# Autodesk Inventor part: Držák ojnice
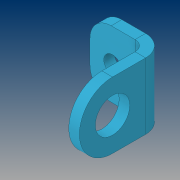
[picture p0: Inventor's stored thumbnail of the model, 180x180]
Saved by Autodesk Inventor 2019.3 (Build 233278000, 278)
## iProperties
Created: 2019-02
Part Number: Držák ojnice
Material: Ocel, legovaná
Document SubType Name: Plech
Designer: B-hon
Density: 7.73 g/cm^3
Sheet Metal Rule: Výchozí_mm
Appearance: Tyrkysová
Author: B-hon
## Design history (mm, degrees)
node "Plocha1"
  sketch "Náčrt1"
    geometry: L1 (-12.5, 12.5)-(12.5, 12.5); L2 (12.5, 12.5)-(12.5, -12.5); L3 (12.5, -12.5)-(-12.5, -12.5); L4 (-12.5, -12.5)-(-12.5, 12.5); L5 (-12.5, 12.5)-(12.5, -12.5); L6 (12.5, 12.5)-(-12.5, -12.5); 1 further point
    constraints: 12 end point, 2 midpoint, 2 parallel, 1 horizontal, 1 perpendicular
    dimensions: "d0" = 25 distance of L2.end L3.end; "d1" = 25 distance of L1.end L2.end
node "Obruba1"
fillet "Zaoblení1" dims "d13" = 12.5
sketch "Náčrt3"
  geometry: A1 r 12.5 centre (12.5, 12.5) between (12.5, 0) and (12.5, 25) reference; 2 further points
  constraints: 1 coincident
hole "Díra1" sketch "Náčrt3" at (12.5, 12.5) diameter "d14" = 13; stored, may be unused: countersink angle "d18" = 90 deg, drill point angle "d20" = 118 deg; dims "d15" = 6, "d16" = 10.5, "d17" = 2, "d19" = 4 (= Tloušťka)
fillet "Zaoblení2" dims "d21" = 8
sketch "Náčrt4"
  geometry: L1 (-12.5, -4.5)-(-12.5, 4.5) reference; L2 (-4.5, 12.5)-(4.5, 12.5) reference; 2 further points
  dimensions: "d22" = 8.5 distance from line of L1 point (-4, 0); "d23" = 12.5 distance from line of L2 point (-4, 0)
hole "Díra2" sketch "Náčrt4" at (-4, 0) diameter "d24" = 6.6; stored, may be unused: countersink angle "d28" = 90 deg, drill point angle "d30" = 118 deg; dims "d25" = 6, "d26" = 10.5, "d27" = 2, "d29" = 4 (= Tloušťka)
node "Těleso1"
feature "Deska1" dims "d2" = 4 (= Tloušťka)
sketch "Náčrt2"
  geometry: L1 through (-12.5, 0) direction (1, 0); L2 through (0, 16.5) direction (0, 1); L3 (0, 33)-(-25, 33); L4 (-25, 33)-(-25, 0)
  constraints: 6 end point, 1 horizontal, 1 perpendicular, 1 vertical
feature "Deska2" dims "d2" = 4 (= Tloušťka), "d3" = 4 (= ŠířkaVýštipu), "d4" = 2 (= HloubkaVýštipu), "d5" = 8 (= MinimálníZbytek), "d6" = 4 (= PřechodovýPoloměr), "d7" = 33, "d8" = 90 deg, "d9" = 4 (= PoloměrOhybu), "d10" = 16 (= VelikostRohovéhoVýštipu), "d11" = 4 (= VelikostMezery), "d12" = 4 (= VelikostJacobihoPoloměru), "MezeraVystřižení" = 0.01
feature "Ohyb1" dims "d2" = 4 (= Tloušťka), "d3" = 4 (= ŠířkaVýštipu), "d4" = 2 (= HloubkaVýštipu), "d5" = 8 (= MinimálníZbytek), "d6" = 4 (= PřechodovýPoloměr), "d7" = 33, "d8" = 90 deg, "d9" = 4 (= PoloměrOhybu), "MezeraVystřižení" = 0.01
feature "Roh1" dims "d7" = 33, "d8" = 90 deg, "d10" = 16 (= VelikostRohovéhoVýštipu), "d11" = 4 (= VelikostMezery), "d12" = 4 (= VelikostJacobihoPoloměru)
other parameters: "Tloušťka" = 4 (derived), "KSoučinitel" = 4.4, "PoloměrOhybu" = 4 (= Tloušťka), "ŠířkaVýštipu" = 4 (= Tloušťka), "HloubkaVýštipu" = 2 (= 0.5 x Tloušťka), "VelikostRohovéhoVýštipu" = 16 (= 4 x Tloušťka), "MinimálníZbytek" = 8 (= 2 x Tloušťka), "PřechodovýPoloměr" = 4 (= PoloměrOhybu), "VelikostJacobihoPoloměru" = 4 (= PoloměrOhybu), "VelikostMezery" = 4 (= Tloušťka)
